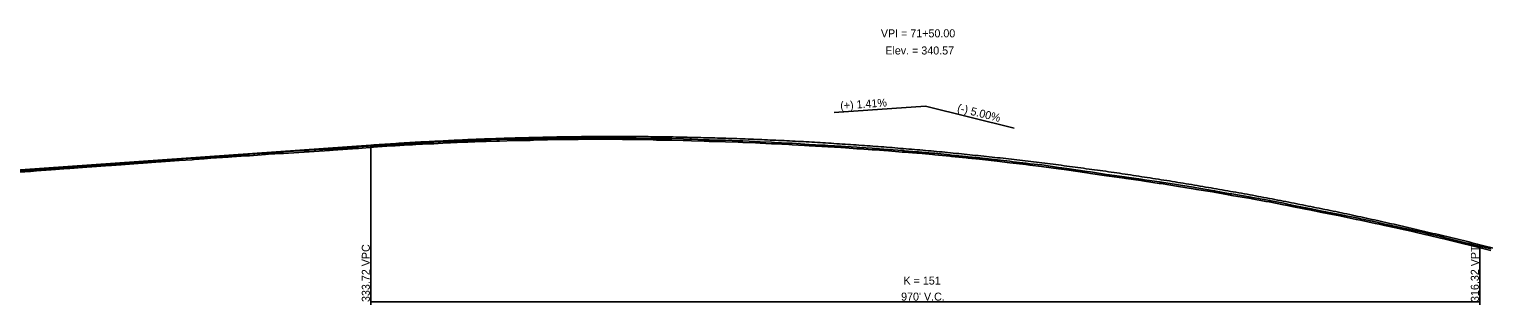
# Model space of a CAD drawing. Extents: x 1876258 to 1926563, y 729739 to 834437.
# Drawn here: x 1884729 to 1886002, y 831533 to 831774 of the extents above; entities that cross this region are included whole.
import ezdxf

# ---------------------------------------------------------------- set-up
doc = ezdxf.new("R2010")
doc.units = 0
for name, color, linetype in [('RD_EX_BldgApp', 7, 'Continuous'), ('RD_EX_H2O_BlueLn', 7, 'Continuous'), ('RD_EX_RailRoad', 7, 'Continuous'), ('RD_HC_Data', 7, 'Continuous'), ('RD_HC_Data_Tic', 7, 'Continuous'), ('RD_HC_TX_Sta50', 7, 'Continuous'), ('RD_PD_ALT5_CL', 7, 'Continuous')]:
    doc.layers.add(name, color=color, linetype=linetype)

msp = doc.modelspace()

# ---------------------------------------------------------------- linework, layer by layer
at = {"layer": 'RD_EX_BldgApp'}
for points in [[(1884720.5, 831649.3), (1884730.4, 831650), (1884735.6, 831650.4), (1884744, 831651), (1884748.5, 831651.3), (1884759.6, 831652.2), (1884764.6, 831652.5), (1884779.5, 831653.6), (1884784, 831653.9), (1884796, 831654.8), (1884801.1, 831655.1), (1884809.7, 831655.7), (1884813.1, 831655.9), (1884824.6, 831656.8), (1884829, 831657.1), (1884839.9, 831657.9), (1884844.5, 831658.3), (1884856.4, 831659.2), (1884860.3, 831659.5), (1884871.6, 831660.2), (1884873.5, 831660.3), (1884882.3, 831660.9), (1884888, 831661.4), (1884903.1, 831662.4), (1884906.4, 831662.6), (1884918.8, 831663.5), (1884922, 831663.7), (1884935.8, 831664.7), (1884938.4, 831664.9), (1884949.5, 831665.6), (1884951.6, 831665.7), (1884969.6, 831666.9), (1884971.9, 831667), (1884974.2, 831667.1), (1884991.9, 831668.1), (1884995.2, 831668.4), (1885012, 831669.7), (1885014.5, 831669.9), (1885017.3, 831670.1), (1885030.3, 831671.1), (1885033.8, 831671.3), (1885046, 831672.2), (1885049.2, 831672.4), (1885061.3, 831673.1), (1885064.3, 831673.2), (1885067.3, 831673.4), (1885079.3, 831674), (1885083, 831674.2), (1885094.8, 831674.8), (1885097.7, 831674.9), (1885109.6, 831675.4), (1885112.9, 831675.6), (1885125.3, 831676), (1885128.8, 831676.2), (1885138.2, 831676.4), (1885140.6, 831676.5), (1885153.8, 831676.9), (1885156.2, 831677), (1885167.5, 831677.1), (1885170.2, 831677.2), (1885179, 831677.5), (1885182.6, 831677.5), (1885191.9, 831677.7), (1885195, 831677.7), (1885205.1, 831677.8), (1885209.2, 831677.8), (1885220, 831678), (1885223.2, 831678), (1885233, 831678), (1885236.1, 831678), (1885245.3, 831678), (1885248.1, 831677.9), (1885257.1, 831677.7), (1885260.2, 831677.7), (1885274.8, 831677.5), (1885278, 831677.4), (1885287.7, 831677.4), (1885291.3, 831677.3), (1885301.3, 831677.1), (1885305, 831677), (1885308.5, 831676.8), (1885319.4, 831676.3), (1885323.8, 831676.2), (1885334.4, 831676), (1885338.2, 831675.9), (1885349.4, 831675.5), (1885353.4, 831675.3), (1885364.4, 831674.9), (1885368.6, 831674.7), (1885378.3, 831674.2), (1885381, 831674.1), (1885393.5, 831673.5), (1885396.5, 831673.3), (1885407.4, 831672.6)], [(1885407.4, 831672.6), (1885411.4, 831672.4), (1885422.4, 831671.8), (1885425.2, 831671.6), (1885427.7, 831671.5), (1885439.2, 831670.8), (1885443.2, 831670.5), (1885453.1, 831669.8), (1885455.7, 831669.6), (1885466.5, 831668.9), (1885468.7, 831668.8), (1885480.7, 831667.9), (1885492.8, 831666.9), (1885493.7, 831666.9), (1885494.4, 831666.8), (1885505.6, 831665.9), (1885507, 831665.8), (1885519.2, 831664.7), (1885521.2, 831664.5), (1885534.3, 831663.2), (1885534.5, 831663.2), (1885535.9, 831663), (1885548.7, 831661.7), (1885550.4, 831661.5), (1885560.5, 831660.6), (1885563, 831660.3), (1885573.3, 831659.2), (1885575.8, 831659), (1885586.8, 831657.6), (1885589.7, 831657.2), (1885600.9, 831655.9), (1885604.4, 831655.4), (1885614.6, 831654.4), (1885616.7, 831654.1), (1885629.4, 831652.2), (1885632.2, 831651.9), (1885636.5, 831651.3), (1885654.2, 831648.7), (1885657.3, 831648.2), (1885671.3, 831646.2), (1885673.9, 831645.8), (1885686.9, 831644), (1885688.6, 831643.7), (1885701.6, 831641.9), (1885703.1, 831641.6), (1885704.6, 831641.4), (1885717.5, 831639.5), (1885719.2, 831639.3), (1885732.6, 831637.2), (1885734.3, 831636.9), (1885747.3, 831634.8), (1885748.8, 831634.6), (1885750.2, 831634.3), (1885764.1, 831632.1), (1885765.7, 831631.8), (1885778, 831629.5), (1885779.5, 831629.3), (1885780.9, 831629), (1885797.6, 831626.2), (1885798.8, 831625.9), (1885810.9, 831623.8), (1885813.8, 831623.3), (1885826.2, 831620.9), (1885829.8, 831620.2), (1885833.4, 831619.4), (1885845.6, 831617), (1885849, 831616.3), (1885859.9, 831614), (1885864.4, 831613.2), (1885875.5, 831611.1), (1885879.3, 831610.3), (1885889.9, 831608.1), (1885893.6, 831607.3), (1885906.5, 831604.6), (1885910, 831603.8), (1885914.7, 831602.8), (1885924.6, 831600.7), (1885928.3, 831599.9), (1885938, 831597.7), (1885941.5, 831597), (1885949.9, 831595), (1885952.7, 831594.3), (1885963.7, 831591.8), (1885966.6, 831591.1), (1885975.7, 831588.8), (1885980.5, 831587.6), (1885991.3, 831584.9), (1885995.9, 831583.8), (1886007.5, 831581)]]:
    msp.add_lwpolyline(points, dxfattribs=at)
at = {"layer": 'RD_EX_H2O_BlueLn'}
for p, q in [((1885028.1, 831533.4), (1885028.1, 831672.9)), ((1885998.1, 831533.4), (1885998.1, 831585.9)), ((1885028.1, 831535.9), (1885998.1, 831535.9))]:
    msp.add_line(p, q, dxfattribs=at)
at = {"layer": 'RD_HC_Data_Tic'}
msp.add_lwpolyline([(1884720.4, 831650.6), (1884730.3, 831651.2), (1884735.5, 831651.6), (1884743.9, 831652.2), (1884748.4, 831652.6), (1884759.5, 831653.4), (1884764.5, 831653.8), (1884779.4, 831654.8), (1884783.9, 831655.1), (1884795.9, 831656), (1884801, 831656.3), (1884809.6, 831656.9), (1884813, 831657.2), (1884824.5, 831658.1), (1884828.9, 831658.4), (1884839.8, 831659.1), (1884844.4, 831659.5), (1884856.3, 831660.4), (1884860.2, 831660.7), (1884871.5, 831661.4), (1884873.4, 831661.6), (1884882.2, 831662.2), (1884887.9, 831662.6), (1884903, 831663.6), (1884906.3, 831663.9), (1884918.7, 831664.8), (1884921.9, 831665), (1884935.7, 831666), (1884938.3, 831666.1), (1884949.4, 831666.9), (1884951.6, 831667), (1884969.5, 831668.1), (1884971.8, 831668.3), (1884974.1, 831668.4), (1884991.8, 831669.4), (1884995.1, 831669.6), (1885012, 831671), (1885014.4, 831671.1), (1885017.2, 831671.4), (1885030.2, 831672.3), (1885033.7, 831672.6), (1885045.9, 831673.4), (1885049.1, 831673.6), (1885061.2, 831674.3), (1885064.2, 831674.5), (1885067.2, 831674.6), (1885079.2, 831675.3), (1885083, 831675.5), (1885094.8, 831676), (1885097.7, 831676.1), (1885109.6, 831676.7), (1885112.8, 831676.8), (1885125.3, 831677.3), (1885128.7, 831677.4), (1885138.2, 831677.7), (1885140.6, 831677.7), (1885153.7, 831678.2), (1885156.2, 831678.2), (1885167.5, 831678.4), (1885170.1, 831678.4), (1885179, 831678.7), (1885182.5, 831678.8), (1885191.9, 831678.9), (1885195, 831679), (1885205.1, 831679), (1885209.2, 831679.1), (1885220, 831679.2), (1885223.2, 831679.2), (1885233, 831679.2), (1885236.1, 831679.3), (1885245.3, 831679.2), (1885248.1, 831679.2), (1885257.1, 831679), (1885260.2, 831678.9), (1885274.8, 831678.7), (1885278, 831678.7), (1885287.7, 831678.6), (1885291.3, 831678.6), (1885301.4, 831678.3), (1885305, 831678.2), (1885308.6, 831678.1), (1885319.5, 831677.6), (1885323.8, 831677.5), (1885334.5, 831677.3), (1885338.2, 831677.2), (1885349.5, 831676.8), (1885353.4, 831676.6), (1885364.4, 831676.1), (1885368.6, 831675.9), (1885378.3, 831675.5), (1885381, 831675.3), (1885393.5, 831674.7), (1885396.6, 831674.5), (1885407.5, 831673.8), (1885411.5, 831673.6), (1885422.5, 831673), (1885425.3, 831672.9), (1885427.8, 831672.7), (1885439.3, 831672), (1885443.3, 831671.7), (1885453.1, 831671.1), (1885455.8, 831670.9), (1885466.5, 831670.2), (1885468.7, 831670), (1885480.8, 831669.1), (1885492.9, 831668.2), (1885493.8, 831668.1), (1885494.6, 831668), (1885505.7, 831667.1), (1885507.1, 831667), (1885519.3, 831665.9), (1885521.3, 831665.8), (1885534.3, 831664.4), (1885534.5, 831664.4), (1885536, 831664.3), (1885548.8, 831662.9), (1885550.5, 831662.8), (1885560.6, 831661.8), (1885563.1, 831661.6), (1885573.4, 831660.5), (1885576, 831660.2), (1885586.9, 831658.8), (1885589.8, 831658.4), (1885601.1, 831657.1), (1885604.6, 831656.7), (1885614.8, 831655.6), (1885616.9, 831655.3), (1885629.6, 831653.5), (1885632.4, 831653.1), (1885636.6, 831652.6), (1885654.4, 831649.9), (1885657.5, 831649.5), (1885671.5, 831647.4), (1885674.1, 831647), (1885687.1, 831645.2), (1885688.8, 831645), (1885701.8, 831643.1), (1885703.3, 831642.9), (1885704.8, 831642.7), (1885717.7, 831640.8), (1885719.4, 831640.5), (1885732.8, 831638.4), (1885734.5, 831638.1), (1885747.5, 831636.1), (1885749, 831635.8), (1885750.4, 831635.6), (1885764.2, 831633.3), (1885765.9, 831633.1), (1885778.2, 831630.8), (1885779.7, 831630.5), (1885781.1, 831630.3), (1885797.9, 831627.4), (1885799, 831627.2), (1885811.1, 831625), (1885814, 831624.5), (1885826.4, 831622.1), (1885830, 831621.4), (1885833.7, 831620.6), (1885845.9, 831618.2), (1885849.2, 831617.5), (1885860.2, 831615.2), (1885864.7, 831614.4), (1885875.8, 831612.3), (1885879.6, 831611.5), (1885890.1, 831609.3), (1885893.8, 831608.5), (1885906.8, 831605.8), (1885910.3, 831605), (1885915, 831604), (1885924.9, 831601.9), (1885928.6, 831601.1), (1885938.3, 831598.9), (1885941.8, 831598.2), (1885950.2, 831596.2), (1885953, 831595.5), (1885964, 831593), (1885966.9, 831592.3), (1885976, 831590), (1885980.8, 831588.8), (1885991.6, 831586.1), (1885996.2, 831585), (1886007.8, 831582.3)], dxfattribs=at)
at = {"layer": 'RD_HC_TX_Sta50'}
for p in [(1885433.3, 831701.5), (1885590.7, 831687.7)]:
    msp.add_line(p, (1885513.1, 831707.1), dxfattribs=at)
at = {"layer": 'RD_PD_ALT5_CL'}
for p, q in [((1884343.1, 831624.5), (1885028.1, 831672.9)), ((1885998.1, 831585.9), (1886165.1, 831544.1))]:
    msp.add_line(p, q, dxfattribs=at)
msp.add_spline([(1885028.1, 831672.9), (1885047.5, 831674.2), (1885066.9, 831675.4), (1885086.3, 831676.4), (1885105.7, 831677.4), (1885125.1, 831678.2), (1885144.5, 831678.9), (1885163.9, 831679.4), (1885183.3, 831679.9), (1885202.7, 831680.2), (1885222.1, 831680.4), (1885241.5, 831680.4), (1885260.9, 831680.4), (1885280.3, 831680.2), (1885299.7, 831679.9), (1885319.1, 831679.4), (1885338.5, 831678.9), (1885357.9, 831678.2), (1885377.3, 831677.4), (1885396.7, 831676.5), (1885416.1, 831675.4), (1885435.5, 831674.2), (1885454.9, 831672.9), (1885474.3, 831671.5), (1885493.7, 831669.9), (1885513.1, 831668.3), (1885532.5, 831666.5), (1885551.9, 831664.5), (1885571.3, 831662.5), (1885590.7, 831660.3), (1885610.1, 831658), (1885629.5, 831655.6), (1885648.9, 831653), (1885668.3, 831650.4), (1885687.7, 831647.6), (1885707.1, 831644.6), (1885726.5, 831641.6), (1885745.9, 831638.4), (1885765.3, 831635.1), (1885784.7, 831631.7), (1885804.1, 831628.2), (1885823.5, 831624.5), (1885842.9, 831620.7), (1885862.3, 831616.8), (1885881.7, 831612.8), (1885901.1, 831608.6), (1885920.5, 831604.3), (1885939.9, 831599.9), (1885959.3, 831595.3), (1885978.7, 831590.7), (1885998.1, 831585.9)], degree=3, dxfattribs=at)

# ---------------------------------------------------------------- texts
at = {"layer": 'RD_EX_H2O_BlueLn'}
for s, p in [('K = 151', (1885493.9, 831551.1)), ("970' V.C.", (1885491.8, 831537.1))]:
    msp.add_text(s, height=7, dxfattribs=at).set_placement(p)
at = {"layer": 'RD_EX_RailRoad'}
for s, p in [('333.72 VPC', (1885027.1, 831535.9)), ('316.32 VPT', (1885997.1, 831535.9))]:
    msp.add_text(s, height=7, rotation=90, dxfattribs=at).set_placement(p)
at = {"layer": 'RD_HC_Data'}
for s, p in [('VPI = 71+50.00', (1885474.1, 831767.1)), ('Elev. = 340.57', (1885478, 831752.1))]:
    msp.add_text(s, height=7, dxfattribs=at).set_placement(p)
at = {"layer": 'RD_HC_TX_Sta50'}
for s, rotation, p in [('(+) 1.41%', 4.041, (1885438.8, 831703.9)), ('(-) 5.00%', 345.9638, (1885540.4, 831702.4))]:
    msp.add_text(s, height=7, rotation=rotation, dxfattribs=at).set_placement(p)

doc.saveas('drawing.dxf')
